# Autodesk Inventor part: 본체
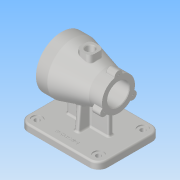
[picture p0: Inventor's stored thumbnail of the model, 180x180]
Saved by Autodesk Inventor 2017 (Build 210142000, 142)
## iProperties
Part Number: 본체
Material: 알루미늄 6061
Document SubType Name: Modeling
Designer: user
Density: 2.7 g/cm^3
Appearance: 알루미늄 - 평지
Mass: 1235.3 g
Surface Area: 902.299 cm^2
Volume: 457.517 cm^3
Author: user
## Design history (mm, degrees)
sketch "스케치1"
  geometry: L1 (70, 55)-(-70, 55); L2 (-70, 55)-(-70, -55); L3 (-70, -55)-(70, -55); L4 (70, -55)-(70, 55); L5 (70, 55)-(-70, -55); L6 (-70, 55)-(70, -55); 1 further point
  constraints: 12 end point, 2 midpoint, 2 parallel, 1 horizontal, 1 perpendicular
  dimensions: "d0" = 140 distance of L3.end L2.end; "d1" = 110 distance of L2.end L1.end
extrude "돌출1" new body sketch "스케치1" distance "d2" = 12; taper "d3" = 0 deg
sketch "스케치2"
  geometry: L1 (-37, -4)-(37, -4); L2 (37, -4)-(37, 4); L3 (37, 4)-(-37, 4); L4 (-37, 4)-(-37, -4); L5 (-37, -4)-(37, 4); L6 (37, -4)-(-37, 4); L7 (-4, -24)-(4, -24); L8 (4, -24)-(4, 24); L9 (4, 24)-(-4, 24); L10 (-4, 24)-(-4, -24); L11 (-4, -24)-(4, 24); 1 further point
  constraints: 22 end point, 4 parallel, 3 midpoint, 2 horizontal, 2 perpendicular
  dimensions: "d4" = 74 distance of L3.end L2.end; "d5" = 8 distance of L2.end L1.end; "d6" = 8 distance of L9.end L8.end; "d89" = 24 distance from line of L7 point (0, 0); "d90" = 24 distance from line of L9 point (0, 0)
extrude "돌출2" join sketch "스케치2" distance "d8" = 82; taper "d9" = 0 deg
feature "면 기울기1" dims angle "d10" = 5 deg
sketch "스케치3"
  geometry: L1 (-50, 82)-(50, 82); L2 (50, 82)-(50, 111); L3 (50, 111)-(27, 111); L4 (27, 111)-(-30, 127); L5 (-30, 127)-(-50, 127); L6 (-50, 127)-(-50, 82); L7 (70, 0)-(-70, 0) reference; 3 further points
  constraints: 12 end point, 3 perpendicular, 2 midpoint, 1 horizontal, 1 parallel, 1 vertical alignment
  dimensions: "d11" = 82 distance between parallel lines of L1 L7; "d12" = 58 diameter of L3 L1; "d13" = 90 diameter of L5 L1; "d14" = 20 distance of L4.end L5.end; "d15" = 23 distance of L3.end L2.end; "d16" = 100 distance between parallel lines of L2 L6
revolve "회전1" sketch "스케치3" stored, may be unused: angle "d17" = 90 deg
sketch "스케치4"
  geometry: L1 (0, 0)-(0, 29); L2 (0, 0)-(-25.115, -14.5); L3 (0, 0)-(25.115, -14.5); C1 r 7 at (0, 29); C2 r 7 at (-25.115, -14.5); C3 r 7 at (25.115, -14.5); A1 r 29 centre (0, 0) between (0, 29) and (-25.115, -14.5) reference; 1 further point
  constraints: 6 end point, 3 centre point, 3 coincident, 3 point on circle, 1 vertical
  dimensions: "d18" = 120 deg angle of L2 L1; "d20" = 120 deg angle of L3 L1; "d21" = 14 diameter of C1; "d22" = 14 diameter of C2; "d23" = 14 diameter of C3
extrude "돌출3" join sketch "스케치4" distance "d24" = 15; taper "d25" = 0 deg
node "작업 평면1"
sketch "스케치5"
  geometry: L1 (12.5, 12.5)-(-12.5, 12.5); L2 (-12.5, 12.5)-(-12.5, -12.5); L3 (-12.5, -12.5)-(12.5, -12.5); L4 (12.5, -12.5)-(12.5, 12.5); L5 (12.5, 12.5)-(-12.5, -12.5); L6 (-12.5, 12.5)-(12.5, -12.5); L7 (50, 45)-(50, -45) reference; 3 further points
  constraints: 12 end point, 3 midpoint, 2 parallel, 1 coincident, 1 horizontal, 1 perpendicular
  dimensions: "d27" = 25 distance of L3.end L2.end; "d28" = 25 distance of L2.end L1.end; "d29" = 50 distance from line of point (0, 0) L7
extrude "돌출4" join sketch "스케치5" stored distance "d30" = 15; taper "d31" = 0 deg
sketch "스케치6"
  geometry: L1 (-50, 37)-(-50, 127) reference; L2 (-50, 82)-(50, 82); L3 (50, 73.94)-(50, 110.155) reference; L4 (-50, 82)-(-50, 113); L5 (-50, 113)-(-30, 113); L6 (-27, 110)-(-27, 110); L7 (-30, 37.178)-(-30, 127) reference; L8 (-24, 107)-(17, 107); L9 (20, 104)-(20, 104); L10 (23, 101)-(50, 101); L11 (50, 101)-(50, 82); A1 r 3 centre (-30, 110) between (-27, 110) and (-30, 113); A2 r 3 centre (-24, 110) between (-27, 110) and (-24, 107); A3 r 3 centre (17, 104) between (20, 104) and (17, 107); A4 r 3 centre (23, 104) between (20, 104) and (23, 101); 1 further point
  constraints: 16 end point, 8 point on circle, 8 tangent, 4 centre point, 3 equal radius, 3 perpendicular, 3 point on line, 2 horizontal, 1 collinear, 1 midpoint, 1 parallel
  dimensions: "d32" = 62 diameter of L5 L2; "d33" = 50 diameter of L8 L2; "d34" = 38 diameter of L10 L2; "d35" = 23 distance between parallel lines of L6 L1; "d36" = 47 distance between parallel lines of L9 L6; "d37" = 3 radius of A1
revolve "회전2" sketch "스케치6" stored, may be unused: angle "d38" = 90 deg
sketch "스케치7"
  geometry: C1 r 7.5 at (0, 0); 1 further point
  constraints: 1 centre point, 1 coincident
  dimensions: "d39" = 15 diameter of C1
extrude "돌출5" cut sketch "스케치7" stored distance "d40" = 15; taper "d41" = 0 deg
sketch "스케치8"
  geometry: A1 r 7 centre (0, 0) between (6.949, -0.845) and (-6.949, -0.845) reference; A2 r 7 centre (-25.115, -43.5) between (-27.858, -37.06) and (-20.909, -49.095) reference; A3 r 7 centre (25.115, -43.5) between (20.909, -49.095) and (27.858, -37.06) reference; 4 further points
  constraints: 3 coincident
hole "구멍1" sketch "스케치8" at (0, 0), (-25.115, -43.5), (25.115, -43.5) diameter "d42" = 3.242; stored, may be unused: countersink angle "d46" = 90 deg, drill point angle "d48" = 118 deg; dims "d43" = 9, "d44" = 4, "d45" = 2, "d47" = 11
sketch "스케치9"
  geometry: L1 (0, 0)-(0, 40); L2 (0, 0)-(-34.641, 20); L3 (0, 0)-(-34.641, -20); L4 (0, 0)-(0, -40); L5 (0, 0)-(34.641, 20); L6 (0, 0)-(34.641, -20); C1 r 45 at (0, 0) reference; A1 r 40 centre (0, 0) between (0, 40) and (-34.641, 20); 7 further points
  constraints: 12 end point, 7 coincident, 6 point on circle, 2 point on line, 1 centre point, 1 vertical
  dimensions: "d49" = 80 diameter of A1; "d50" = 60 deg angle of L2 L1; "d51" = 60 deg angle of L3 L2; "d52" = 60 deg angle of L5 L1
hole "구멍2" sketch "스케치9" at (34.641, 20), (34.641, -20), (0, 40), (-34.641, 20), (-34.641, -20), (0, -40) diameter "d53" = 3.242; stored, may be unused: countersink angle "d57" = 90 deg, drill point angle "d59" = 118 deg; dims "d54" = 9, "d55" = 4, "d56" = 2, "d58" = 11
fillet "모깎기1" dims "d60" = 16
sketch "스케치10"
  geometry: C1 r 9 at (-54, 39); C2 r 9 at (54, 39); C3 r 9 at (-54, -39); C4 r 9 at (54, -39); A1 r 16 centre (54, 39) between (70, 39) and (54, 55) reference; A2 r 16 centre (-54, 39) between (-54, 55) and (-70, 39) reference; A3 r 16 centre (-54, -39) between (-70, -39) and (-54, -55) reference; A4 r 16 centre (54, -39) between (54, -55) and (70, -39) reference; 1 further point
  constraints: 4 centre point, 4 coincident
  dimensions: "d61" = 18 diameter of C1; "d62" = 18 diameter of C2; "d63" = 18 diameter of C3; "d64" = 18 diameter of C4
extrude "돌출6" cut sketch "스케치10" distance "d65" = 2; taper "d66" = 0 deg
sketch "스케치11"
  geometry: C1 r 4.5 at (54, 39); C2 r 4.5 at (54, -39); C3 r 4.5 at (-54, 39); C4 r 4.5 at (-54, -39); A1 r 16 centre (54, -39) between (54, -55) and (70, -39) reference; A2 r 16 centre (54, 39) between (70, 39) and (54, 55) reference; A3 r 16 centre (-54, 39) between (-54, 55) and (-70, 39) reference; A4 r 16 centre (-54, -39) between (-70, -39) and (-54, -55) reference; 1 further point
  constraints: 4 centre point, 4 coincident
  dimensions: "d67" = 9 diameter of C1; "d68" = 9 diameter of C2; "d69" = 9 diameter of C3; "d70" = 9 diameter of C4
extrude "돌출7" cut sketch "스케치11" distance "d71" = 10; taper "d72" = 0 deg
fillet "모깎기2" dims "d73" = 8
fillet "모깎기3" dims "d74" = 1
chamfer "모따기1" distance "d75" = 1; stored, may be unused: second distance "d76" = 2, angle "d77" = 45 deg
fillet "모깎기4" dims "d78" = 3
fillet "모깎기5" dims "d79" = 1
fillet "모깎기6" dims "d80" = 3
fillet "모깎기7" dims "d81" = 3
chamfer "모따기2" distance "d82" = 1; stored, may be unused: second distance "d83" = 2, angle "d84" = 45 deg
node "작업 평면2"
sketch "스케치12"
  geometry: L1 (54, 55)-(-54, 55) reference; 2 further points
  constraints: 1 vertical alignment, 1 other
  dimensions: "d86" = 15 distance from line of point (0, 40) L1
feature "엠보싱1" sketch "스케치12" dims "d0" = 140, "d1" = 110, "d87" = 0.5, "d88" = 0
node "솔리드1"
other parameters: "d26" = 127, "d85" = 22
